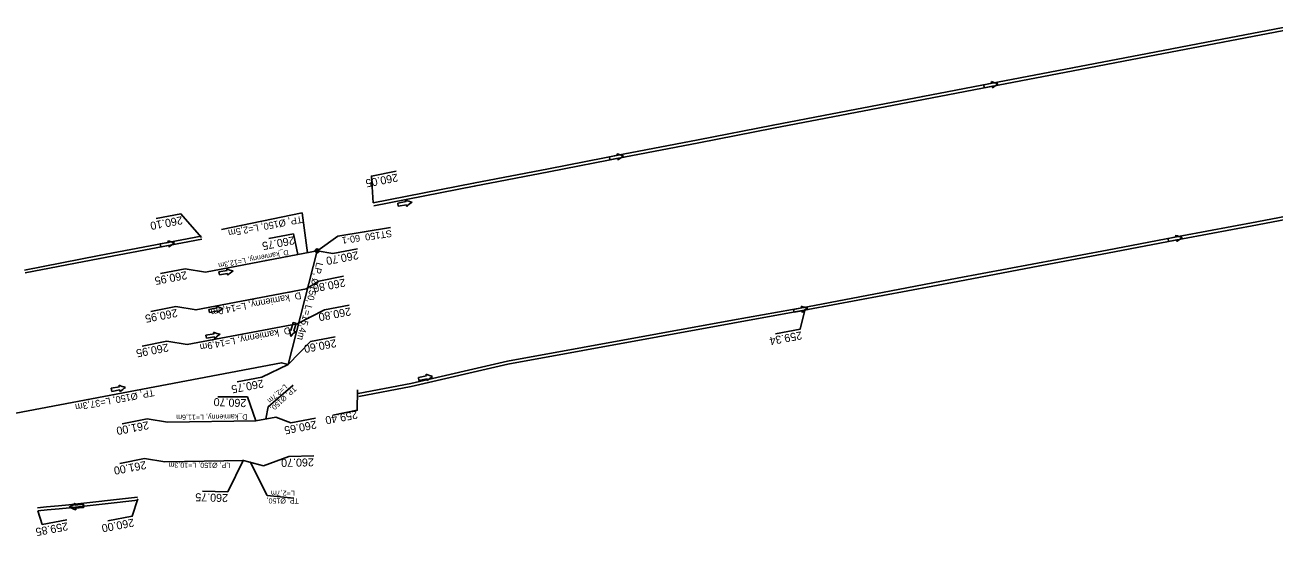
# Model space of a CAD drawing. Extents: x -1 to 65640748, y -22 to 5530284.
# Drawn here: x 6558970 to 6559133.8, y 5528943.7 to 5529010.7 of the extents above; entities that cross this region are included whole.
import ezdxf

# ---------------------------------------------------------------- set-up
doc = ezdxf.new("R2010")
doc.units = 0
for name, color, linetype in [('TOR_PROF-studnie i osadniki', 7, 'Continuous'), ('TOR_PS_ODW-drenaze', 7, 'Continuous'), ('TOR_PS_ODW-drenokolektory', 7, 'Continuous'), ('TOR_PS_ODW-studnie PEHD', 7, 'Continuous'), ('TOR_PS_OPIS_O-opisy rurociagow', 7, 'Continuous'), ('TOR_PS_OPIS_O-opisy studni', 7, 'Continuous'), ('TOR_PS_OPIS_T-INFO', 7, 'Continuous'), ('TOR_PS_T-rowy otwarte umocnione', 7, 'Continuous')]:
    doc.layers.add(name, color=color, linetype=linetype)

msp = doc.modelspace()

# ---------------------------------------------------------------- linework, layer by layer
at = {"layer": 'TOR_PROF-studnie i osadniki'}
for radius in [0.25, 0.125]:
    msp.add_circle((6559008.33, 5528981.1), radius, dxfattribs=at)
at = {"layer": 'TOR_PS_ODW-drenaze'}
for p, q in [((6558993.72, 5528978.33), (6559005.83, 5528980.63)), ((6559008.33, 5528981.1), (6559004.53, 5528966.18)), ((6558992.45, 5528973.36), (6559006.94, 5528976.1)), ((6558991.29, 5528968.81), (6559005.72, 5528971.55)), ((6558988.7, 5528958.64), (6559000.31, 5528958.8))]:
    msp.add_line(p, q, dxfattribs=at)
for points in [[(6559004.53, 5528966.18), (6559008.33, 5528981.1)], [(6559004.53, 5528966.18), (6559003.65, 5528966.42), (6558967.92, 5528959.65)], [(6558988.36, 5528953.43), (6558998.67, 5528953.6)]]:
    msp.add_lwpolyline(points, dxfattribs=at)
at = {"layer": 'TOR_PS_ODW-drenokolektory'}
for p, q in [((6559005.83, 5528980.63), (6559008.33, 5528981.1)), ((6559000.31, 5528958.8), (6559002.94, 5528959.3))]:
    msp.add_line(p, q, dxfattribs=at)
msp.add_lwpolyline([(6558998.67, 5528953.6), (6559001.31, 5528952.89)], dxfattribs=at)
at = {"layer": 'TOR_PS_ODW-studnie PEHD'}
for radius in [0.25, 0.112]:
    msp.add_circle((6559008.33, 5528981.1), radius, dxfattribs=at)
at = {"layer": 'TOR_PS_OPIS_O-opisy rurociagow'}
for p, q in [((6559096.84, 5529003.09), (6559095.76, 5529002.88)), ((6559096.84, 5529003.09), (6559095.76, 5529002.88)), ((6559095.76, 5529002.88), (6559095.84, 5529002.49)), ((6559095.76, 5529002.88), (6559095.84, 5529002.49)), ((6559095.84, 5529002.49), (6559096.91, 5529002.7)), ((6559096.91, 5529002.7), (6559095.84, 5529002.49)), ((6559047.74, 5528993.64), (6559046.67, 5528993.43)), ((6559047.74, 5528993.64), (6559046.67, 5528993.43)), ((6559046.67, 5528993.43), (6559046.74, 5528993.04)), ((6559046.67, 5528993.43), (6559046.74, 5528993.04)), ((6559046.74, 5528993.04), (6559047.82, 5528993.25)), ((6559047.82, 5528993.25), (6559046.74, 5528993.04)), ((6559020, 5528987.56), (6559018.92, 5528987.37)), ((6559020, 5528987.56), (6559018.92, 5528987.37)), ((6559018.92, 5528987.37), (6559018.99, 5528986.97)), ((6559018.92, 5528987.37), (6559018.99, 5528986.97)), ((6559018.99, 5528986.97), (6559020.07, 5528987.16)), ((6559020.07, 5528987.16), (6559018.99, 5528986.97)), ((6558988.83, 5528982.22), (6558987.76, 5528982.01)), ((6558988.83, 5528982.22), (6558987.76, 5528982.01)), ((6558987.76, 5528982.01), (6558987.84, 5528981.62)), ((6558987.76, 5528982.01), (6558987.84, 5528981.62)), ((6558987.84, 5528981.62), (6558988.91, 5528981.82)), ((6558988.91, 5528981.82), (6558987.84, 5528981.62)), ((6559121.02, 5528982.93), (6559119.95, 5528982.72)), ((6559121.02, 5528982.93), (6559119.95, 5528982.72)), ((6559119.95, 5528982.72), (6559120.02, 5528982.33)), ((6559119.95, 5528982.72), (6559120.02, 5528982.33)), ((6559120.02, 5528982.33), (6559121.09, 5528982.53)), ((6559121.09, 5528982.53), (6559120.02, 5528982.33)), ((6558996.53, 5528978.53), (6558995.46, 5528978.34)), ((6558996.53, 5528978.53), (6558995.46, 5528978.34)), ((6558995.46, 5528978.34), (6558995.53, 5528977.95)), ((6558995.46, 5528978.34), (6558995.53, 5528977.95)), ((6558995.53, 5528977.95), (6558996.6, 5528978.14)), ((6558996.6, 5528978.14), (6558995.53, 5528977.95)), ((6558995.21, 5528973.62), (6558994.14, 5528973.43)), ((6558995.21, 5528973.62), (6558994.14, 5528973.43)), ((6558994.14, 5528973.43), (6558994.21, 5528973.03)), ((6558994.14, 5528973.43), (6558994.21, 5528973.03)), ((6559071.89, 5528973.64), (6559070.82, 5528973.43)), ((6559071.89, 5528973.64), (6559070.82, 5528973.43)), ((6559070.82, 5528973.43), (6559070.89, 5528973.04)), ((6559070.82, 5528973.43), (6559070.89, 5528973.04)), ((6558994.21, 5528973.03), (6558995.28, 5528973.22)), ((6558995.28, 5528973.22), (6558994.21, 5528973.03)), ((6559070.89, 5528973.04), (6559071.96, 5528973.24)), ((6559071.96, 5528973.24), (6559070.89, 5528973.04)), ((6558994.82, 5528970.22), (6558993.74, 5528970.03)), ((6558994.82, 5528970.22), (6558993.74, 5528970.03)), ((6559005.2, 5528971.71), (6559004.9, 5528970.66)), ((6559004.9, 5528970.66), (6559005.2, 5528971.71)), ((6559005.58, 5528971.6), (6559005.2, 5528971.71)), ((6559005.58, 5528971.6), (6559005.2, 5528971.71)), ((6559005.28, 5528970.55), (6559005.58, 5528971.6)), ((6559005.28, 5528970.55), (6559005.58, 5528971.6)), ((6558993.74, 5528970.03), (6558993.81, 5528969.64)), ((6558993.74, 5528970.03), (6558993.81, 5528969.64)), ((6558993.81, 5528969.64), (6558994.89, 5528969.83)), ((6558994.89, 5528969.83), (6558993.81, 5528969.64)), ((6559022.7, 5528964.7), (6559021.62, 5528964.5)), ((6559022.7, 5528964.7), (6559021.62, 5528964.5)), ((6559021.62, 5528964.5), (6559021.69, 5528964.11)), ((6559021.62, 5528964.5), (6559021.69, 5528964.11)), ((6559021.69, 5528964.11), (6559022.77, 5528964.3)), ((6559022.77, 5528964.3), (6559021.69, 5528964.11)), ((6558982.41, 5528963.26), (6558981.33, 5528963.07)), ((6558982.41, 5528963.26), (6558981.33, 5528963.07)), ((6558981.33, 5528963.07), (6558981.4, 5528962.67)), ((6558981.33, 5528963.07), (6558981.4, 5528962.67)), ((6558981.4, 5528962.67), (6558982.48, 5528962.86)), ((6558982.48, 5528962.86), (6558981.4, 5528962.67)), ((6558977.67, 5528947.85), (6558976.58, 5528947.75)), ((6558976.58, 5528947.75), (6558977.67, 5528947.85)), ((6558977.67, 5528947.85), (6558976.58, 5528947.75)), ((6558976.58, 5528947.75), (6558977.67, 5528947.85)), ((6558977.7, 5528947.86), (6558976.62, 5528947.75)), ((6558976.62, 5528947.75), (6558977.7, 5528947.86)), ((6558976.62, 5528947.35), (6558977.7, 5528947.45)), ((6558976.62, 5528947.35), (6558977.7, 5528947.45)), ((6558976.62, 5528947.35), (6558977.7, 5528947.45)), ((6558976.62, 5528947.35), (6558977.7, 5528947.45)), ((6558976.65, 5528947.35), (6558977.74, 5528947.46)), ((6558976.65, 5528947.35), (6558977.74, 5528947.46)), ((6558977.7, 5528947.45), (6558977.67, 5528947.85)), ((6558977.7, 5528947.45), (6558977.67, 5528947.85)), ((6558977.7, 5528947.45), (6558977.67, 5528947.85)), ((6558977.7, 5528947.45), (6558977.67, 5528947.85)), ((6558977.74, 5528947.46), (6558977.7, 5528947.86)), ((6558977.74, 5528947.46), (6558977.7, 5528947.86))]:
    msp.add_line(p, q, dxfattribs=at)
for points in [[(6559096.79, 5529003.31), (6559096.79, 5529003.31)], [(6559096.95, 5529002.47), (6559096.95, 5529002.47)], [(6559047.69, 5528993.86), (6559047.69, 5528993.86)], [(6559047.85, 5528993.02), (6559047.85, 5528993.02)], [(6559019.95, 5528987.78), (6559019.95, 5528987.78)], [(6559020.09, 5528986.94), (6559020.09, 5528986.94)], [(6558988.78, 5528982.43), (6558988.78, 5528982.43)], [(6558988.94, 5528981.6), (6558988.94, 5528981.6)], [(6559120.97, 5528983.15), (6559120.97, 5528983.15)], [(6559121.13, 5528982.31), (6559121.13, 5528982.31)], [(6558996.48, 5528978.75), (6558996.48, 5528978.75)], [(6558996.63, 5528977.92), (6558996.63, 5528977.92)], [(6558995.16, 5528973.84), (6558995.16, 5528973.84)], [(6559071.84, 5528973.86), (6559071.84, 5528973.86)], [(6558995.31, 5528973), (6558995.31, 5528973)], [(6559072, 5528973.02), (6559072, 5528973.02)], [(6558994.77, 5528970.44), (6558994.77, 5528970.44)], [(6559004.69, 5528970.73), (6559004.69, 5528970.73)], [(6559005.5, 5528970.5), (6559005.5, 5528970.5)], [(6558994.92, 5528969.6), (6558994.92, 5528969.6)], [(6559022.65, 5528964.92), (6559022.65, 5528964.92)], [(6559022.8, 5528964.08), (6559022.8, 5528964.08)], [(6558982.36, 5528963.48), (6558982.36, 5528963.48)], [(6558982.51, 5528962.64), (6558982.51, 5528962.64)], [(6558976.57, 5528947.97), (6558976.57, 5528947.97)], [(6558976.57, 5528947.97), (6558976.57, 5528947.97)], [(6558976.6, 5528947.98), (6558976.6, 5528947.98)], [(6558976.65, 5528947.13), (6558976.65, 5528947.13)], [(6558976.65, 5528947.13), (6558976.65, 5528947.13)], [(6558976.69, 5528947.13), (6558976.69, 5528947.13)]]:
    msp.add_lwpolyline(points, dxfattribs=at)
for centre, radius, start, end in [((6559098.7, 5529007.84), 4.92, 247.1116, 257.4934), ((6559097.24, 5529003.3), 0.458, 179.2261, 207.6874), ((6559098.7, 5529007.84), 4.92, 247.1116, 257.4934), ((6559097.24, 5529003.3), 0.458, 179.2261, 207.6874), ((6559100.39, 5528998.97), 4.92, 124.1495, 134.5313), ((6559100.39, 5528998.97), 4.92, 124.1495, 134.5313), ((6559097.37, 5529002.65), 0.458, 173.9555, 202.4167), ((6559097.37, 5529002.65), 0.458, 173.9555, 202.4167), ((6559049.58, 5528998.39), 4.92, 247.2848, 257.6666), ((6559048.14, 5528993.85), 0.458, 179.3994, 207.8606), ((6559049.58, 5528998.39), 4.92, 247.2848, 257.6666), ((6559048.14, 5528993.85), 0.458, 179.3994, 207.8606), ((6559048.27, 5528993.2), 0.458, 174.1287, 202.59), ((6559048.27, 5528993.2), 0.458, 174.1287, 202.59), ((6559051.31, 5528989.53), 4.92, 124.3227, 134.7045), ((6559051.31, 5528989.53), 4.92, 124.3227, 134.7045), ((6559021.92, 5528992.28), 4.92, 246.381, 256.7628), ((6559020.4, 5528987.77), 0.458, 178.4955, 206.9568), ((6559021.92, 5528992.28), 4.92, 246.381, 256.7628), ((6559020.4, 5528987.77), 0.458, 178.4955, 206.9568), ((6559020.52, 5528987.11), 0.458, 173.2249, 201.6861), ((6559020.52, 5528987.11), 0.458, 173.2249, 201.6861), ((6559023.5, 5528983.39), 4.92, 123.4189, 133.8007), ((6559023.5, 5528983.39), 4.92, 123.4189, 133.8007), ((6558990.69, 5528986.97), 4.92, 247.1495, 257.5313), ((6558989.24, 5528982.43), 0.458, 179.264, 207.7253), ((6558990.69, 5528986.97), 4.92, 247.1495, 257.5313), ((6558989.24, 5528982.43), 0.458, 179.264, 207.7253), ((6558989.37, 5528981.77), 0.458, 173.9934, 202.4546), ((6558989.37, 5528981.77), 0.458, 173.9934, 202.4546), ((6558992.39, 5528978.1), 4.92, 124.1873, 134.5692), ((6558992.39, 5528978.1), 4.92, 124.1873, 134.5692), ((6559122.89, 5528987.67), 4.92, 246.9983, 257.3802), ((6559121.43, 5528983.14), 0.458, 179.1129, 207.5741), ((6559122.89, 5528987.67), 4.92, 246.9983, 257.3802), ((6559121.43, 5528983.14), 0.458, 179.1129, 207.5741), ((6559121.55, 5528982.49), 0.458, 173.8423, 202.3035), ((6559121.55, 5528982.49), 0.458, 173.8423, 202.3035), ((6559124.57, 5528978.8), 4.92, 124.0362, 134.4181), ((6559124.57, 5528978.8), 4.92, 124.0362, 134.4181), ((6558998.45, 5528983.26), 4.92, 246.381, 256.7628), ((6558996.94, 5528978.74), 0.458, 178.4955, 206.9568), ((6558998.45, 5528983.26), 4.92, 246.381, 256.7628), ((6558996.94, 5528978.74), 0.458, 178.4955, 206.9568), ((6559000.04, 5528974.37), 4.92, 123.4189, 133.8007), ((6559000.04, 5528974.37), 4.92, 123.4189, 133.8007), ((6558997.06, 5528978.08), 0.458, 173.2249, 201.6861), ((6558997.06, 5528978.08), 0.458, 173.2249, 201.6861), ((6558997.13, 5528978.34), 4.92, 246.381, 256.7628), ((6558995.62, 5528973.82), 0.458, 178.4955, 206.9568), ((6558997.13, 5528978.34), 4.92, 246.381, 256.7628), ((6558995.62, 5528973.82), 0.458, 178.4955, 206.9568), ((6558998.71, 5528969.45), 4.92, 123.4189, 133.8007), ((6558998.71, 5528969.45), 4.92, 123.4189, 133.8007), ((6559073.76, 5528978.38), 4.92, 246.9983, 257.3802), ((6559072.3, 5528973.85), 0.458, 179.1129, 207.5741), ((6559073.76, 5528978.38), 4.92, 246.9983, 257.3802), ((6559072.3, 5528973.85), 0.458, 179.1129, 207.5741), ((6559075.44, 5528969.51), 4.92, 124.0362, 134.418), ((6559075.44, 5528969.51), 4.92, 124.0362, 134.418), ((6558995.74, 5528973.17), 0.458, 173.2249, 201.6861), ((6558995.74, 5528973.17), 0.458, 173.2249, 201.6861), ((6559072.42, 5528973.19), 0.458, 173.8422, 202.3035), ((6559072.42, 5528973.19), 0.458, 173.8422, 202.3035), ((6558996.74, 5528974.95), 4.92, 246.381, 256.7628), ((6558995.22, 5528970.43), 0.458, 178.4955, 206.9568), ((6558996.74, 5528974.95), 4.92, 246.381, 256.7628), ((6558995.22, 5528970.43), 0.458, 178.4955, 206.9568), ((6558998.32, 5528966.05), 4.92, 123.4189, 133.8007), ((6558998.32, 5528966.05), 4.92, 123.4189, 133.8007), ((6559004.65, 5528970.28), 0.458, 57.1627, 85.624), ((6559000, 5528969.23), 4.92, 7.3567, 17.7385), ((6559000, 5528969.23), 4.92, 7.3567, 17.7385), ((6559004.65, 5528970.28), 0.458, 57.1627, 85.624), ((6559008.68, 5528966.75), 4.92, 130.3188, 140.7006), ((6559008.68, 5528966.75), 4.92, 130.3188, 140.7006), ((6559005.29, 5528970.09), 0.458, 62.4334, 90.8946), ((6559005.29, 5528970.09), 0.458, 62.4334, 90.8946), ((6558995.34, 5528969.77), 0.458, 173.2249, 201.6861), ((6558995.34, 5528969.77), 0.458, 173.2249, 201.6861), ((6559024.6, 5528969.43), 4.92, 246.5959, 256.9778), ((6559023.1, 5528964.91), 0.458, 178.7105, 207.1717), ((6559024.6, 5528969.43), 4.92, 246.5959, 256.9778), ((6559023.1, 5528964.91), 0.458, 178.7105, 207.1717), ((6559023.22, 5528964.25), 0.458, 173.4399, 201.9011), ((6559023.22, 5528964.25), 0.458, 173.4399, 201.9011), ((6559026.21, 5528960.54), 4.92, 123.6338, 134.0157), ((6559026.21, 5528960.54), 4.92, 123.6338, 134.0157), ((6558984.33, 5528967.98), 4.92, 246.381, 256.7628), ((6558982.82, 5528963.47), 0.458, 178.4955, 206.9568), ((6558984.33, 5528967.98), 4.92, 246.381, 256.7628), ((6558982.82, 5528963.47), 0.458, 178.4955, 206.9568), ((6558982.93, 5528962.81), 0.458, 173.2249, 201.6861), ((6558982.93, 5528962.81), 0.458, 173.2249, 201.6861), ((6558985.91, 5528959.09), 4.92, 123.4189, 133.8007), ((6558985.91, 5528959.09), 4.92, 123.4189, 133.8007), ((6558973.46, 5528951.79), 4.92, 298.7792, 309.161), ((6558973.46, 5528951.79), 4.92, 298.7792, 309.161), ((6558973.46, 5528951.79), 4.92, 298.7792, 309.161), ((6558973.46, 5528951.79), 4.92, 298.7792, 309.161), ((6558974.32, 5528942.79), 4.92, 61.7413, 72.1231), ((6558974.32, 5528942.79), 4.92, 61.7413, 72.1231), ((6558974.32, 5528942.79), 4.92, 61.7413, 72.1231), ((6558974.32, 5528942.79), 4.92, 61.7413, 72.1231), ((6558973.5, 5528951.79), 4.92, 298.7792, 309.161), ((6558973.5, 5528951.79), 4.92, 298.7792, 309.161), ((6558974.36, 5528942.8), 4.92, 61.7413, 72.1231), ((6558974.36, 5528942.8), 4.92, 61.7413, 72.1231), ((6558976.13, 5528947.84), 0.458, 348.5852, 17.0465), ((6558976.13, 5528947.84), 0.458, 348.5852, 17.0465), ((6558976.13, 5528947.84), 0.458, 348.5852, 17.0465), ((6558976.13, 5528947.84), 0.458, 348.5852, 17.0465), ((6558976.17, 5528947.84), 0.458, 348.5852, 17.0465), ((6558976.17, 5528947.84), 0.458, 348.5852, 17.0465), ((6558976.19, 5528947.18), 0.458, 353.8559, 22.3171), ((6558976.19, 5528947.18), 0.458, 353.8559, 22.3171), ((6558976.19, 5528947.18), 0.458, 353.8559, 22.3171), ((6558976.19, 5528947.18), 0.458, 353.8559, 22.3171), ((6558976.23, 5528947.18), 0.458, 353.8559, 22.3171), ((6558976.23, 5528947.18), 0.458, 353.8559, 22.3171)]:
    msp.add_arc(centre, radius, start, end, dxfattribs=at)
at = {"layer": 'TOR_PS_OPIS_T-INFO'}
for points in [[(6559018.71, 5528991.55), (6559015.47, 5528990.92), (6559015.71, 5528987.42)], [(6558993.17, 5528982.85), (6558990.47, 5528985.95), (6558987.23, 5528985.33)], [(6558995.78, 5528983.9), (6559006.37, 5528986.08), (6559007.08, 5528980.86)], [(6559002, 5528982.72), (6559005.23, 5528983.32), (6559005.83, 5528980.63)], [(6559008.43, 5528981.17), (6559011.06, 5528983.03), (6559017.96, 5528984.18)], [(6559008.33, 5528981.1), (6559010.38, 5528980.77), (6559013.62, 5528981.37)], [(6558993.72, 5528978.33), (6558991.04, 5528978.74), (6558987.81, 5528978.12)], [(6559011.82, 5528977.77), (6559008.58, 5528977.14), (6559006.92, 5528976.1)], [(6558992.46, 5528973.37), (6558989.79, 5528973.79), (6558986.55, 5528973.16)], [(6559012.53, 5528973.98), (6559009.3, 5528973.36), (6559005.71, 5528971.54)], [(6559072.37, 5528973.48), (6559071.7, 5528970.85), (6559068.47, 5528970.23)], [(6558991.29, 5528968.83), (6558988.62, 5528969.24), (6558985.38, 5528968.62)], [(6559004.53, 5528966.18), (6559007.48, 5528969.23), (6559010.72, 5528969.83)], [(6559004.53, 5528966.18), (6559001.1, 5528964.52), (6558997.87, 5528963.9)], [(6559000.31, 5528958.8), (6558999.2, 5528961.94), (6558995.32, 5528961.96)], [(6559001.62, 5528959.05), (6559001.93, 5528960.65), (6559005.22, 5528963.49)], [(6559013.65, 5528962.86), (6559013.61, 5528960.18), (6559010.38, 5528959.56)], [(6558988.7, 5528958.64), (6558986.03, 5528959.05), (6558982.79, 5528958.43)], [(6559002.94, 5528959.3), (6559004.89, 5528958.54), (6559008.12, 5528959.14)], [(6558988.36, 5528953.43), (6558985.69, 5528953.84), (6558982.45, 5528953.22)], [(6559001.31, 5528952.89), (6559004.62, 5528954.14), (6559007.91, 5528954.2)], [(6558998.68, 5528953.69), (6558996.61, 5528949.5), (6558993.31, 5528949.59)], [(6558999.54, 5528953.44), (6559001.79, 5528949.01), (6559005.3, 5528948.67)], [(6558984.81, 5528948.58), (6558984.1, 5528946.28), (6558980.87, 5528945.66)], [(6558971.69, 5528946.98), (6558972.28, 5528945.2), (6558975.52, 5528945.8)]]:
    msp.add_lwpolyline(points, dxfattribs=at)
at = {"layer": 'TOR_PS_T-rowy otwarte umocnione'}
for points in [[(6559136.88, 5529010.74), (6559127.06, 5529008.87), (6559117.24, 5529006.99), (6559107.42, 5529005.11), (6559097.59, 5529003.23), (6559087.77, 5529001.36), (6559077.95, 5528999.48), (6559068.13, 5528997.6), (6559058.31, 5528995.69), (6559048.5, 5528993.79), (6559038.68, 5528991.88), (6559028.86, 5528989.97), (6559015.71, 5528987.42)], [(6559136.96, 5529010.35), (6559127.14, 5529008.47), (6559117.31, 5529006.6), (6559107.49, 5529004.72), (6559097.67, 5529002.84), (6559087.85, 5529000.96), (6559078.02, 5528999.09), (6559068.2, 5528997.21), (6559058.39, 5528995.3), (6559048.57, 5528993.39), (6559038.75, 5528991.49), (6559028.94, 5528989.58), (6559015.79, 5528987.02)], [(6559141.42, 5528986.79), (6559131.6, 5528984.93), (6559121.77, 5528983.07), (6559111.95, 5528981.21), (6559102.12, 5528979.35), (6559092.3, 5528977.5), (6559082.47, 5528975.64), (6559072.64, 5528973.78), (6559062.8, 5528971.99), (6559052.97, 5528970.2), (6559043.13, 5528968.41), (6559033.29, 5528966.62), (6559020.61, 5528963.7), (6559013.73, 5528962.4)], [(6559141.5, 5528986.39), (6559131.67, 5528984.53), (6559121.85, 5528982.68), (6559112.02, 5528980.82), (6559102.2, 5528978.96), (6559092.37, 5528977.1), (6559082.54, 5528975.24), (6559072.72, 5528973.39), (6559062.88, 5528971.6), (6559053.04, 5528969.81), (6559043.2, 5528968.02), (6559033.36, 5528966.23), (6559020.68, 5528963.31), (6559013.81, 5528962.01)], [(6558993.13, 5528983.04), (6558979.77, 5528980.48), (6558969.95, 5528978.59)], [(6558993.21, 5528982.65), (6558979.85, 5528980.08), (6558970.03, 5528978.2)], [(6558975.79, 5528947.78), (6558974.42, 5528947.65), (6558972.85, 5528947.5), (6558971.65, 5528947.38)], [(6558975.87, 5528947.38), (6558974.49, 5528947.26), (6558972.92, 5528947.11), (6558971.69, 5528946.98)], [(6558975.79, 5528947.78), (6558984.8, 5528948.78)], [(6558975.87, 5528947.38), (6558984.82, 5528948.38)]]:
    msp.add_lwpolyline(points, dxfattribs=at)

# ---------------------------------------------------------------- texts
at = {"layer": 'TOR_PS_OPIS_O-opisy rurociagow'}
for s, height, rotation, p in [('TP, Ø150, L=2,5m', 0.9, 190.7332, (6559006.3, 5528985.68)), ('D_kamienny, L=12,3m', 0.675, 190.7332, (6559004.52, 5528981.24)), ('LP, Ø150, L=15,4m', 0.9, 255.7031, (6559008.27, 5528979.66)), ('D_kamienny, L=14,9m', 0.9, 190.7332, (6559006.17, 5528975.69)), ('D_kamienny, L=14,9m', 0.9, 190.7332, (6559004.75, 5528971.11)), (' L=2,7m', 0.675, 222.4963, (6559004.25, 5528963.83)), ('TP, Ø150, L=37,3m', 0.9, 190.7332, (6558986.89, 5528962.95)), ('TP, Ø150,', 0.675, 222.4963, (6559005.25, 5528963.37)), ('D_kamienny, L=11,6m', 0.675, 180.3326, (6558999.2, 5528959.65)), ('LP, Ø150, L=10,3m', 0.675, 179.7173, (6558996.95, 5528953.29)), ('L=2,7m', 0.675, 179.7173, (6559005.41, 5528949.64)), ('TP, Ø150, ', 0.675, 179.7173, (6559005.96, 5528948.62))]:
    msp.add_text(s, height=height, rotation=rotation, dxfattribs=at).set_placement(p)
at = {"layer": 'TOR_PS_OPIS_O-opisy studni'}
msp.add_text('ST150_60-1', height=0.9, rotation=188.2224, dxfattribs=at).set_placement((6559018.08, 5528983.84))
at = {"layer": 'TOR_PS_OPIS_T-INFO'}
for s, rotation, p in [('260.05', 190.7159, (6559018.84, 5528991.25)), ('260.10', 190.7159, (6558990.6, 5528985.66)), ('260.75', 190.7506, (6559005.27, 5528983.02)), ('260.70', 190.7506, (6559013.66, 5528981.07)), ('260.95', 190.7159, (6558991.18, 5528978.45)), ('260.80', 190.7159, (6559011.95, 5528977.47)), ('260.95', 190.7159, (6558989.92, 5528973.49)), ('260.80', 190.7159, (6559012.67, 5528973.69)), ('259.34', 190.7159, (6559071.83, 5528970.55)), ('260.95', 190.7159, (6558988.75, 5528968.95)), ('260.60', 190.7506, (6559010.76, 5528969.53)), ('260.75', 190.7159, (6559001.23, 5528964.23)), ('260.70', 177.8979, (6558999.08, 5528961.64)), ('261.00', 190.7159, (6558986.16, 5528958.76)), ('260.65', 190.7506, (6559008.17, 5528958.84)), ('259.40', 190.7159, (6559013.56, 5528960.15)), ('260.70', 181.1582, (6559007.9, 5528953.89)), ('261.00', 190.7159, (6558985.82, 5528953.54)), ('260.75', 178.205, (6558996.67, 5528949.18)), ('260.00', 190.7159, (6558984.23, 5528945.98)), ('259.85', 190.7506, (6558975.56, 5528945.5))]:
    msp.add_text(s, height=1.05, rotation=rotation, dxfattribs=at).set_placement(p)

doc.saveas('drawing.dxf')
